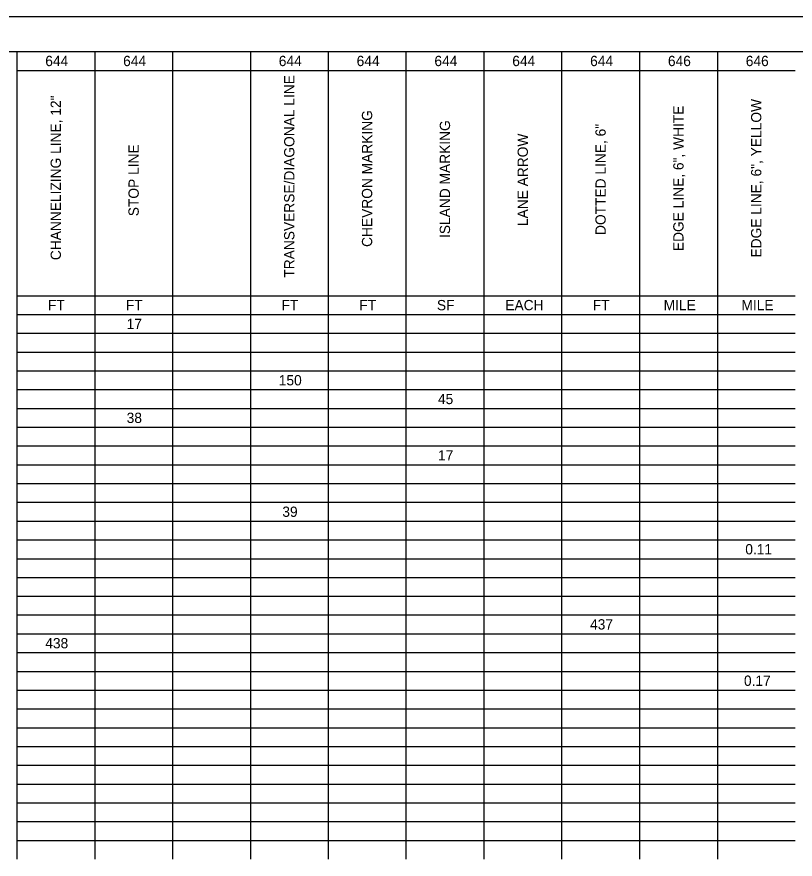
# Model space of a CAD drawing. Extents: x 0 to 34, y 0 to 22.
# Drawn here: x 14.09 to 25.28, y 9.88 to 22 of the extents above; entities that cross this region are included whole.
import ezdxf

# ---------------------------------------------------------------- set-up
doc = ezdxf.new("R2010")
doc.units = 0
for name, color, linetype in [('SH_Border', 7, 'Continuous'), ('SH_Cut_Line', 7, 'Continuous'), ('SH_Data', 7, 'Continuous')]:
    doc.layers.add(name, color=color, linetype=linetype)

msp = doc.modelspace()

# ---------------------------------------------------------------- linework, layer by layer
at = {"layer": 'SH_Border'}
msp.add_lwpolyline([(1.5, 21.5), (33.5, 21.5), (33.5, 0.5), (1.5, 0.5)], close=True, dxfattribs=at)
at = {"layer": 'SH_Cut_Line'}
msp.add_lwpolyline([(0, 0), (34, 0), (34, 22), (0, 22)], close=True, dxfattribs=at)
at = {"layer": 'SH_Data'}
for p, q in [((14.086, 21.5), (15.206, 21.5)), ((14.086, 21.5), (14.086, 21.23)), ((15.206, 21.5), (16.325, 21.5)), ((15.206, 21.5), (15.206, 21.23)), ((16.325, 21.5), (24.163, 21.5)), ((16.325, 21.5), (16.325, 21.23)), ((17.445, 21.5), (17.445, 21.23)), ((18.565, 21.5), (18.565, 21.23)), ((19.684, 21.5), (19.684, 21.23)), ((20.804, 21.5), (20.804, 21.23)), ((21.923, 21.5), (21.923, 21.23)), ((23.043, 21.5), (23.043, 21.23)), ((24.163, 21.5), (25.282, 21.5)), ((24.163, 21.5), (24.163, 21.23)), ((14.086, 21.23), (15.206, 21.23)), ((14.086, 21.23), (14.086, 20.96)), ((15.206, 21.23), (16.325, 21.23)), ((15.206, 21.23), (15.206, 20.96)), ((16.325, 21.23), (24.163, 21.23)), ((16.325, 21.23), (16.325, 20.96)), ((17.445, 21.23), (17.445, 20.96)), ((18.565, 21.23), (18.565, 20.96)), ((19.684, 21.23), (19.684, 20.96)), ((20.804, 21.23), (20.804, 20.96)), ((21.923, 21.23), (21.923, 20.96)), ((23.043, 21.23), (23.043, 20.96)), ((24.163, 21.23), (25.282, 21.23)), ((24.163, 21.23), (24.163, 20.96)), ((14.086, 20.96), (14.086, 20.69)), ((15.206, 20.96), (15.206, 20.69)), ((16.325, 20.96), (16.325, 20.69)), ((17.445, 20.96), (17.445, 20.69)), ((18.565, 20.96), (18.565, 20.69)), ((19.684, 20.96), (19.684, 20.69)), ((20.804, 20.96), (20.804, 20.69)), ((21.923, 20.96), (21.923, 20.69)), ((23.043, 20.96), (23.043, 20.69)), ((24.163, 20.96), (24.163, 20.69)), ((14.086, 20.69), (14.086, 20.419)), ((15.206, 20.69), (15.206, 20.419)), ((16.325, 20.69), (16.325, 20.419)), ((17.445, 20.69), (17.445, 20.419)), ((18.565, 20.69), (18.565, 20.419)), ((19.684, 20.69), (19.684, 20.419)), ((20.804, 20.69), (20.804, 20.419)), ((21.923, 20.69), (21.923, 20.419)), ((23.043, 20.69), (23.043, 20.419)), ((24.163, 20.69), (24.163, 20.419)), ((14.086, 20.419), (14.086, 20.149)), ((15.206, 20.419), (15.206, 20.149)), ((16.325, 20.419), (16.325, 20.149)), ((17.445, 20.419), (17.445, 20.149)), ((18.565, 20.419), (18.565, 20.149)), ((19.684, 20.419), (19.684, 20.149)), ((20.804, 20.419), (20.804, 20.149)), ((21.923, 20.419), (21.923, 20.149)), ((23.043, 20.419), (23.043, 20.149)), ((24.163, 20.419), (24.163, 20.149)), ((14.086, 20.149), (14.086, 19.879)), ((15.206, 20.149), (15.206, 19.879)), ((16.325, 20.149), (16.325, 19.879)), ((17.445, 20.149), (17.445, 19.879)), ((18.565, 20.149), (18.565, 19.879)), ((19.684, 20.149), (19.684, 19.879)), ((20.804, 20.149), (20.804, 19.879)), ((21.923, 20.149), (21.923, 19.879)), ((23.043, 20.149), (23.043, 19.879)), ((24.163, 20.149), (24.163, 19.879)), ((14.086, 19.879), (14.086, 19.609)), ((15.206, 19.879), (15.206, 19.609)), ((16.325, 19.879), (16.325, 19.609)), ((17.445, 19.879), (17.445, 19.609)), ((18.565, 19.879), (18.565, 19.609)), ((19.684, 19.879), (19.684, 19.609)), ((20.804, 19.879), (20.804, 19.609)), ((21.923, 19.879), (21.923, 19.609)), ((23.043, 19.879), (23.043, 19.609)), ((24.163, 19.879), (24.163, 19.609)), ((14.086, 19.609), (14.086, 19.338)), ((15.206, 19.609), (15.206, 19.338)), ((16.325, 19.609), (16.325, 19.338)), ((17.445, 19.609), (17.445, 19.338)), ((18.565, 19.609), (18.565, 19.338)), ((19.684, 19.609), (19.684, 19.338)), ((20.804, 19.609), (20.804, 19.338)), ((21.923, 19.609), (21.923, 19.338)), ((23.043, 19.609), (23.043, 19.338)), ((24.163, 19.609), (24.163, 19.338)), ((14.086, 19.338), (14.086, 19.068)), ((15.206, 19.338), (15.206, 19.068)), ((16.325, 19.338), (16.325, 19.068)), ((17.445, 19.338), (17.445, 19.068)), ((18.565, 19.338), (18.565, 19.068)), ((19.684, 19.338), (19.684, 19.068)), ((20.804, 19.338), (20.804, 19.068)), ((21.923, 19.338), (21.923, 19.068)), ((23.043, 19.338), (23.043, 19.068)), ((24.163, 19.338), (24.163, 19.068)), ((14.086, 19.068), (14.086, 18.798)), ((15.206, 19.068), (15.206, 18.798)), ((16.325, 19.068), (16.325, 18.798)), ((17.445, 19.068), (17.445, 18.798)), ((18.565, 19.068), (18.565, 18.798)), ((19.684, 19.068), (19.684, 18.798)), ((20.804, 19.068), (20.804, 18.798)), ((21.923, 19.068), (21.923, 18.798)), ((23.043, 19.068), (23.043, 18.798)), ((24.163, 19.068), (24.163, 18.798)), ((14.086, 18.798), (14.086, 18.528)), ((15.206, 18.798), (15.206, 18.528)), ((16.325, 18.798), (16.325, 18.528)), ((17.445, 18.798), (17.445, 18.528)), ((18.565, 18.798), (18.565, 18.528)), ((19.684, 18.798), (19.684, 18.528)), ((20.804, 18.798), (20.804, 18.528)), ((21.923, 18.798), (21.923, 18.528)), ((23.043, 18.798), (23.043, 18.528)), ((24.163, 18.798), (24.163, 18.528)), ((14.086, 18.528), (14.086, 18.257)), ((15.206, 18.528), (15.206, 18.257)), ((16.325, 18.528), (16.325, 18.257)), ((17.445, 18.528), (17.445, 18.257)), ((18.565, 18.528), (18.565, 18.257)), ((19.684, 18.528), (19.684, 18.257)), ((20.804, 18.528), (20.804, 18.257)), ((21.923, 18.528), (21.923, 18.257)), ((23.043, 18.528), (23.043, 18.257)), ((24.163, 18.528), (24.163, 18.257)), ((14.086, 18.257), (14.086, 17.987)), ((15.206, 18.257), (15.206, 17.987)), ((16.325, 18.257), (16.325, 17.987)), ((17.445, 18.257), (17.445, 17.987)), ((18.565, 18.257), (18.565, 17.987)), ((19.684, 18.257), (19.684, 17.987)), ((20.804, 18.257), (20.804, 17.987)), ((21.923, 18.257), (21.923, 17.987)), ((23.043, 18.257), (23.043, 17.987)), ((24.163, 18.257), (24.163, 17.987)), ((14.086, 17.987), (15.206, 17.987)), ((14.086, 17.987), (14.086, 17.717)), ((15.206, 17.987), (16.325, 17.987)), ((15.206, 17.987), (15.206, 17.717)), ((16.325, 17.987), (24.163, 17.987)), ((16.325, 17.987), (16.325, 17.717)), ((17.445, 17.987), (17.445, 17.717)), ((18.565, 17.987), (18.565, 17.717)), ((19.684, 17.987), (19.684, 17.717)), ((20.804, 17.987), (20.804, 17.717)), ((21.923, 17.987), (21.923, 17.717)), ((23.043, 17.987), (23.043, 17.717)), ((24.163, 17.987), (25.282, 17.987)), ((24.163, 17.987), (24.163, 17.717)), ((14.086, 17.717), (15.206, 17.717)), ((14.086, 17.717), (14.086, 17.447)), ((15.206, 17.717), (16.325, 17.717)), ((15.206, 17.717), (15.206, 17.447)), ((16.325, 17.717), (24.163, 17.717)), ((16.325, 17.717), (16.325, 17.447)), ((17.445, 17.717), (17.445, 17.447)), ((18.565, 17.717), (18.565, 17.447)), ((19.684, 17.717), (19.684, 17.447)), ((20.804, 17.717), (20.804, 17.447)), ((21.923, 17.717), (21.923, 17.447)), ((23.043, 17.717), (23.043, 17.447)), ((24.163, 17.717), (25.282, 17.717)), ((24.163, 17.717), (24.163, 17.447)), ((14.086, 17.447), (15.206, 17.447)), ((14.086, 17.447), (14.086, 17.176)), ((15.206, 17.447), (16.325, 17.447)), ((15.206, 17.447), (15.206, 17.176)), ((16.325, 17.447), (24.163, 17.447)), ((16.325, 17.447), (16.325, 17.176)), ((17.445, 17.447), (17.445, 17.176)), ((18.565, 17.447), (18.565, 17.176)), ((19.684, 17.447), (19.684, 17.176)), ((20.804, 17.447), (20.804, 17.176)), ((21.923, 17.447), (21.923, 17.176)), ((23.043, 17.447), (23.043, 17.176)), ((24.163, 17.447), (25.282, 17.447)), ((24.163, 17.447), (24.163, 17.176)), ((14.086, 17.176), (15.206, 17.176)), ((14.086, 17.176), (14.086, 16.906)), ((15.206, 17.176), (16.325, 17.176)), ((15.206, 17.176), (15.206, 16.906)), ((16.325, 17.176), (24.163, 17.176)), ((16.325, 17.176), (16.325, 16.906)), ((17.445, 17.176), (17.445, 16.906)), ((18.565, 17.176), (18.565, 16.906)), ((19.684, 17.176), (19.684, 16.906)), ((20.804, 17.176), (20.804, 16.906)), ((21.923, 17.176), (21.923, 16.906)), ((23.043, 17.176), (23.043, 16.906)), ((24.163, 17.176), (25.282, 17.176)), ((24.163, 17.176), (24.163, 16.906)), ((14.086, 16.906), (15.206, 16.906)), ((14.086, 16.906), (14.086, 16.636)), ((15.206, 16.906), (16.325, 16.906)), ((15.206, 16.906), (15.206, 16.636)), ((16.325, 16.906), (24.163, 16.906)), ((16.325, 16.906), (16.325, 16.636)), ((17.445, 16.906), (17.445, 16.636)), ((18.565, 16.906), (18.565, 16.636)), ((19.684, 16.906), (19.684, 16.636)), ((20.804, 16.906), (20.804, 16.636)), ((21.923, 16.906), (21.923, 16.636)), ((23.043, 16.906), (23.043, 16.636)), ((24.163, 16.906), (25.282, 16.906)), ((24.163, 16.906), (24.163, 16.636)), ((14.086, 16.636), (15.206, 16.636)), ((14.086, 16.636), (14.086, 16.365)), ((15.206, 16.636), (16.325, 16.636)), ((15.206, 16.636), (15.206, 16.365)), ((16.325, 16.636), (24.163, 16.636)), ((16.325, 16.636), (16.325, 16.365)), ((17.445, 16.636), (17.445, 16.365)), ((18.565, 16.636), (18.565, 16.365)), ((19.684, 16.636), (19.684, 16.365)), ((20.804, 16.636), (20.804, 16.365)), ((21.923, 16.636), (21.923, 16.365)), ((23.043, 16.636), (23.043, 16.365)), ((24.163, 16.636), (25.282, 16.636)), ((24.163, 16.636), (24.163, 16.365)), ((14.086, 16.365), (15.206, 16.365)), ((14.086, 16.365), (14.086, 16.095)), ((15.206, 16.365), (16.325, 16.365)), ((15.206, 16.365), (15.206, 16.095)), ((16.325, 16.365), (24.163, 16.365)), ((16.325, 16.365), (16.325, 16.095)), ((17.445, 16.365), (17.445, 16.095)), ((18.565, 16.365), (18.565, 16.095)), ((19.684, 16.365), (19.684, 16.095)), ((20.804, 16.365), (20.804, 16.095)), ((21.923, 16.365), (21.923, 16.095)), ((23.043, 16.365), (23.043, 16.095)), ((24.163, 16.365), (25.282, 16.365)), ((24.163, 16.365), (24.163, 16.095)), ((14.086, 16.095), (15.206, 16.095)), ((14.086, 16.095), (14.086, 15.825)), ((15.206, 16.095), (16.325, 16.095)), ((15.206, 16.095), (15.206, 15.825)), ((16.325, 16.095), (24.163, 16.095)), ((16.325, 16.095), (16.325, 15.825)), ((17.445, 16.095), (17.445, 15.825)), ((18.565, 16.095), (18.565, 15.825)), ((19.684, 16.095), (19.684, 15.825)), ((20.804, 16.095), (20.804, 15.825)), ((21.923, 16.095), (21.923, 15.825)), ((23.043, 16.095), (23.043, 15.825)), ((24.163, 16.095), (25.282, 16.095)), ((24.163, 16.095), (24.163, 15.825)), ((14.086, 15.825), (15.206, 15.825)), ((14.086, 15.825), (14.086, 15.555)), ((15.206, 15.825), (16.325, 15.825)), ((15.206, 15.825), (15.206, 15.555)), ((16.325, 15.825), (24.163, 15.825)), ((16.325, 15.825), (16.325, 15.555)), ((17.445, 15.825), (17.445, 15.555)), ((18.565, 15.825), (18.565, 15.555)), ((19.684, 15.825), (19.684, 15.555)), ((20.804, 15.825), (20.804, 15.555)), ((21.923, 15.825), (21.923, 15.555)), ((23.043, 15.825), (23.043, 15.555)), ((24.163, 15.825), (25.282, 15.825)), ((24.163, 15.825), (24.163, 15.555)), ((14.086, 15.555), (15.206, 15.555)), ((14.086, 15.555), (14.086, 15.284)), ((15.206, 15.555), (16.325, 15.555)), ((15.206, 15.555), (15.206, 15.284)), ((16.325, 15.555), (24.163, 15.555)), ((16.325, 15.555), (16.325, 15.284)), ((17.445, 15.555), (17.445, 15.284)), ((18.565, 15.555), (18.565, 15.284)), ((19.684, 15.555), (19.684, 15.284)), ((20.804, 15.555), (20.804, 15.284)), ((21.923, 15.555), (21.923, 15.284)), ((23.043, 15.555), (23.043, 15.284)), ((24.163, 15.555), (25.282, 15.555)), ((24.163, 15.555), (24.163, 15.284)), ((14.086, 15.284), (15.206, 15.284)), ((14.086, 15.284), (14.086, 15.014)), ((15.206, 15.284), (16.325, 15.284)), ((15.206, 15.284), (15.206, 15.014)), ((16.325, 15.284), (24.163, 15.284)), ((16.325, 15.284), (16.325, 15.014)), ((17.445, 15.284), (17.445, 15.014)), ((18.565, 15.284), (18.565, 15.014)), ((19.684, 15.284), (19.684, 15.014)), ((20.804, 15.284), (20.804, 15.014)), ((21.923, 15.284), (21.923, 15.014)), ((23.043, 15.284), (23.043, 15.014)), ((24.163, 15.284), (25.282, 15.284)), ((24.163, 15.284), (24.163, 15.014)), ((14.086, 15.014), (15.206, 15.014)), ((14.086, 15.014), (14.086, 14.744)), ((15.206, 15.014), (16.325, 15.014)), ((15.206, 15.014), (15.206, 14.744)), ((16.325, 15.014), (24.163, 15.014)), ((16.325, 15.014), (16.325, 14.744)), ((17.445, 15.014), (17.445, 14.744)), ((18.565, 15.014), (18.565, 14.744)), ((19.684, 15.014), (19.684, 14.744)), ((20.804, 15.014), (20.804, 14.744)), ((21.923, 15.014), (21.923, 14.744)), ((23.043, 15.014), (23.043, 14.744)), ((24.163, 15.014), (25.282, 15.014)), ((24.163, 15.014), (24.163, 14.744)), ((14.086, 14.744), (15.206, 14.744)), ((14.086, 14.744), (14.086, 14.474)), ((15.206, 14.744), (16.325, 14.744)), ((15.206, 14.744), (15.206, 14.474)), ((16.325, 14.744), (24.163, 14.744)), ((16.325, 14.744), (16.325, 14.474)), ((17.445, 14.744), (17.445, 14.474)), ((18.565, 14.744), (18.565, 14.474)), ((19.684, 14.744), (19.684, 14.474)), ((20.804, 14.744), (20.804, 14.474)), ((21.923, 14.744), (21.923, 14.474)), ((23.043, 14.744), (23.043, 14.474)), ((24.163, 14.744), (25.282, 14.744)), ((24.163, 14.744), (24.163, 14.474)), ((14.086, 14.474), (15.206, 14.474)), ((14.086, 14.474), (14.086, 14.203)), ((15.206, 14.474), (16.325, 14.474)), ((15.206, 14.474), (15.206, 14.203)), ((16.325, 14.474), (24.163, 14.474)), ((16.325, 14.474), (16.325, 14.203)), ((17.445, 14.474), (17.445, 14.203)), ((18.565, 14.474), (18.565, 14.203)), ((19.684, 14.474), (19.684, 14.203)), ((20.804, 14.474), (20.804, 14.203)), ((21.923, 14.474), (21.923, 14.203)), ((23.043, 14.474), (23.043, 14.203)), ((24.163, 14.474), (25.282, 14.474)), ((24.163, 14.474), (24.163, 14.203)), ((14.086, 14.203), (15.206, 14.203)), ((14.086, 14.203), (14.086, 13.933)), ((15.206, 14.203), (16.325, 14.203)), ((15.206, 14.203), (15.206, 13.933)), ((16.325, 14.203), (24.163, 14.203)), ((16.325, 14.203), (16.325, 13.933)), ((17.445, 14.203), (17.445, 13.933)), ((18.565, 14.203), (18.565, 13.933)), ((19.684, 14.203), (19.684, 13.933)), ((20.804, 14.203), (20.804, 13.933)), ((21.923, 14.203), (21.923, 13.933)), ((23.043, 14.203), (23.043, 13.933)), ((24.163, 14.203), (25.282, 14.203)), ((24.163, 14.203), (24.163, 13.933)), ((14.086, 13.933), (15.206, 13.933)), ((14.086, 13.933), (14.086, 13.663)), ((15.206, 13.933), (16.325, 13.933)), ((15.206, 13.933), (15.206, 13.663)), ((16.325, 13.933), (24.163, 13.933)), ((16.325, 13.933), (16.325, 13.663)), ((17.445, 13.933), (17.445, 13.663)), ((18.565, 13.933), (18.565, 13.663)), ((19.684, 13.933), (19.684, 13.663)), ((20.804, 13.933), (20.804, 13.663)), ((21.923, 13.933), (21.923, 13.663)), ((23.043, 13.933), (23.043, 13.663)), ((24.163, 13.933), (25.282, 13.933)), ((24.163, 13.933), (24.163, 13.663)), ((14.086, 13.663), (15.206, 13.663)), ((14.086, 13.663), (14.086, 13.393)), ((15.206, 13.663), (16.325, 13.663)), ((15.206, 13.663), (15.206, 13.393)), ((16.325, 13.663), (24.163, 13.663)), ((16.325, 13.663), (16.325, 13.393)), ((17.445, 13.663), (17.445, 13.393)), ((18.565, 13.663), (18.565, 13.393)), ((19.684, 13.663), (19.684, 13.393)), ((20.804, 13.663), (20.804, 13.393)), ((21.923, 13.663), (21.923, 13.393)), ((23.043, 13.663), (23.043, 13.393)), ((24.163, 13.663), (25.282, 13.663)), ((24.163, 13.663), (24.163, 13.393)), ((14.086, 13.393), (15.206, 13.393)), ((14.086, 13.393), (14.086, 13.122)), ((15.206, 13.393), (16.325, 13.393)), ((15.206, 13.393), (15.206, 13.122)), ((16.325, 13.393), (24.163, 13.393)), ((16.325, 13.393), (16.325, 13.122)), ((17.445, 13.393), (17.445, 13.122)), ((18.565, 13.393), (18.565, 13.122)), ((19.684, 13.393), (19.684, 13.122)), ((20.804, 13.393), (20.804, 13.122)), ((21.923, 13.393), (21.923, 13.122)), ((23.043, 13.393), (23.043, 13.122)), ((24.163, 13.393), (25.282, 13.393)), ((24.163, 13.393), (24.163, 13.122)), ((14.086, 13.122), (15.206, 13.122)), ((14.086, 13.122), (14.086, 12.852)), ((15.206, 13.122), (16.325, 13.122)), ((15.206, 13.122), (15.206, 12.852)), ((16.325, 13.122), (24.163, 13.122)), ((16.325, 13.122), (16.325, 12.852)), ((17.445, 13.122), (17.445, 12.852)), ((18.565, 13.122), (18.565, 12.852)), ((19.684, 13.122), (19.684, 12.852)), ((20.804, 13.122), (20.804, 12.852)), ((21.923, 13.122), (21.923, 12.852)), ((23.043, 13.122), (23.043, 12.852)), ((24.163, 13.122), (25.282, 13.122)), ((24.163, 13.122), (24.163, 12.852)), ((14.086, 12.852), (15.206, 12.852)), ((14.086, 12.852), (14.086, 12.582)), ((15.206, 12.852), (16.325, 12.852)), ((15.206, 12.852), (15.206, 12.582)), ((16.325, 12.852), (24.163, 12.852)), ((16.325, 12.852), (16.325, 12.582)), ((17.445, 12.852), (17.445, 12.582)), ((18.565, 12.852), (18.565, 12.582)), ((19.684, 12.852), (19.684, 12.582)), ((20.804, 12.852), (20.804, 12.582)), ((21.923, 12.852), (21.923, 12.582)), ((23.043, 12.852), (23.043, 12.582)), ((24.163, 12.852), (25.282, 12.852)), ((24.163, 12.852), (24.163, 12.582)), ((14.086, 12.582), (15.206, 12.582)), ((14.086, 12.582), (14.086, 12.312)), ((15.206, 12.582), (16.325, 12.582)), ((15.206, 12.582), (15.206, 12.312)), ((16.325, 12.582), (24.163, 12.582)), ((16.325, 12.582), (16.325, 12.312)), ((17.445, 12.582), (17.445, 12.312)), ((18.565, 12.582), (18.565, 12.312)), ((19.684, 12.582), (19.684, 12.312)), ((20.804, 12.582), (20.804, 12.312)), ((21.923, 12.582), (21.923, 12.312)), ((23.043, 12.582), (23.043, 12.312)), ((24.163, 12.582), (25.282, 12.582)), ((24.163, 12.582), (24.163, 12.312)), ((14.086, 12.312), (15.206, 12.312)), ((14.086, 12.312), (14.086, 12.041)), ((15.206, 12.312), (16.325, 12.312)), ((15.206, 12.312), (15.206, 12.041)), ((16.325, 12.312), (24.163, 12.312)), ((16.325, 12.312), (16.325, 12.041)), ((17.445, 12.312), (17.445, 12.041)), ((18.565, 12.312), (18.565, 12.041)), ((19.684, 12.312), (19.684, 12.041)), ((20.804, 12.312), (20.804, 12.041)), ((21.923, 12.312), (21.923, 12.041)), ((23.043, 12.312), (23.043, 12.041)), ((24.163, 12.312), (25.282, 12.312)), ((24.163, 12.312), (24.163, 12.041)), ((14.086, 12.041), (15.206, 12.041)), ((14.086, 12.041), (14.086, 11.771)), ((15.206, 12.041), (16.325, 12.041)), ((15.206, 12.041), (15.206, 11.771)), ((16.325, 12.041), (24.163, 12.041)), ((16.325, 12.041), (16.325, 11.771)), ((17.445, 12.041), (17.445, 11.771)), ((18.565, 12.041), (18.565, 11.771)), ((19.684, 12.041), (19.684, 11.771)), ((20.804, 12.041), (20.804, 11.771)), ((21.923, 12.041), (21.923, 11.771)), ((23.043, 12.041), (23.043, 11.771)), ((24.163, 12.041), (25.282, 12.041)), ((24.163, 12.041), (24.163, 11.771)), ((14.086, 11.771), (15.206, 11.771)), ((14.086, 11.771), (14.086, 11.501)), ((15.206, 11.771), (16.325, 11.771)), ((15.206, 11.771), (15.206, 11.501)), ((16.325, 11.771), (24.163, 11.771)), ((16.325, 11.771), (16.325, 11.501)), ((17.445, 11.771), (17.445, 11.501)), ((18.565, 11.771), (18.565, 11.501)), ((19.684, 11.771), (19.684, 11.501)), ((20.804, 11.771), (20.804, 11.501)), ((21.923, 11.771), (21.923, 11.501)), ((23.043, 11.771), (23.043, 11.501)), ((24.163, 11.771), (25.282, 11.771)), ((24.163, 11.771), (24.163, 11.501)), ((14.086, 11.501), (15.206, 11.501)), ((14.086, 11.501), (14.086, 11.231)), ((15.206, 11.501), (16.325, 11.501)), ((15.206, 11.501), (15.206, 11.231)), ((16.325, 11.501), (24.163, 11.501)), ((16.325, 11.501), (16.325, 11.231)), ((17.445, 11.501), (17.445, 11.231)), ((18.565, 11.501), (18.565, 11.231)), ((19.684, 11.501), (19.684, 11.231)), ((20.804, 11.501), (20.804, 11.231)), ((21.923, 11.501), (21.923, 11.231)), ((23.043, 11.501), (23.043, 11.231)), ((24.163, 11.501), (25.282, 11.501)), ((24.163, 11.501), (24.163, 11.231)), ((14.086, 11.231), (15.206, 11.231)), ((14.086, 11.231), (14.086, 10.96)), ((15.206, 11.231), (16.325, 11.231)), ((15.206, 11.231), (15.206, 10.96)), ((16.325, 11.231), (24.163, 11.231)), ((16.325, 11.231), (16.325, 10.96)), ((17.445, 11.231), (17.445, 10.96)), ((18.565, 11.231), (18.565, 10.96)), ((19.684, 11.231), (19.684, 10.96)), ((20.804, 11.231), (20.804, 10.96)), ((21.923, 11.231), (21.923, 10.96)), ((23.043, 11.231), (23.043, 10.96)), ((24.163, 11.231), (25.282, 11.231)), ((24.163, 11.231), (24.163, 10.96)), ((14.086, 10.96), (15.206, 10.96)), ((14.086, 10.96), (14.086, 10.69)), ((15.206, 10.96), (16.325, 10.96)), ((15.206, 10.96), (15.206, 10.69)), ((16.325, 10.96), (24.163, 10.96)), ((16.325, 10.96), (16.325, 10.69)), ((17.445, 10.96), (17.445, 10.69)), ((18.565, 10.96), (18.565, 10.69)), ((19.684, 10.96), (19.684, 10.69)), ((20.804, 10.96), (20.804, 10.69)), ((21.923, 10.96), (21.923, 10.69)), ((23.043, 10.96), (23.043, 10.69)), ((24.163, 10.96), (25.282, 10.96)), ((24.163, 10.96), (24.163, 10.69)), ((14.086, 10.69), (15.206, 10.69)), ((14.086, 10.69), (14.086, 10.42)), ((15.206, 10.69), (16.325, 10.69)), ((15.206, 10.69), (15.206, 10.42)), ((16.325, 10.69), (24.163, 10.69)), ((16.325, 10.69), (16.325, 10.42)), ((17.445, 10.69), (17.445, 10.42)), ((18.565, 10.69), (18.565, 10.42)), ((19.684, 10.69), (19.684, 10.42)), ((20.804, 10.69), (20.804, 10.42)), ((21.923, 10.69), (21.923, 10.42)), ((23.043, 10.69), (23.043, 10.42)), ((24.163, 10.69), (25.282, 10.69)), ((24.163, 10.69), (24.163, 10.42)), ((14.086, 10.42), (15.206, 10.42)), ((14.086, 10.42), (14.086, 10.15)), ((15.206, 10.42), (16.325, 10.42)), ((15.206, 10.42), (15.206, 10.15)), ((16.325, 10.42), (24.163, 10.42)), ((16.325, 10.42), (16.325, 10.15)), ((17.445, 10.42), (17.445, 10.15)), ((18.565, 10.42), (18.565, 10.15)), ((19.684, 10.42), (19.684, 10.15)), ((20.804, 10.42), (20.804, 10.15)), ((21.923, 10.42), (21.923, 10.15)), ((23.043, 10.42), (23.043, 10.15)), ((24.163, 10.42), (25.282, 10.42)), ((24.163, 10.42), (24.163, 10.15)), ((14.086, 10.15), (15.206, 10.15)), ((14.086, 10.15), (14.086, 9.879)), ((15.206, 10.15), (16.325, 10.15)), ((15.206, 10.15), (15.206, 9.879)), ((16.325, 10.15), (24.163, 10.15)), ((16.325, 10.15), (16.325, 9.879)), ((17.445, 10.15), (17.445, 9.879)), ((18.565, 10.15), (18.565, 9.879)), ((19.684, 10.15), (19.684, 9.879)), ((20.804, 10.15), (20.804, 9.879)), ((21.923, 10.15), (21.923, 9.879)), ((23.043, 10.15), (23.043, 9.879)), ((24.163, 10.15), (25.282, 10.15)), ((24.163, 10.15), (24.163, 9.879))]:
    msp.add_line(p, q, dxfattribs=at)

# ---------------------------------------------------------------- texts
for s, p in [('644', (14.495, 21.291)), ('644', (15.615, 21.291)), ('644', (17.854, 21.291)), ('644', (18.974, 21.291)), ('644', (20.093, 21.291)), ('644', (21.213, 21.291)), ('644', (22.333, 21.291)), ('646', (23.452, 21.291)), ('646', (24.572, 21.291)), ('FT', (14.534, 17.778)), ('FT', (15.654, 17.778)), ('FT', (17.893, 17.778)), ('FT', (19.013, 17.778)), ('SF', (20.129, 17.778)), ('EACH', (21.113, 17.778)), ('FT', (22.371, 17.778)), ('MILE', (23.391, 17.778)), ('MILE', (24.51, 17.778)), ('17', (15.666, 17.508)), ('150', (17.854, 16.697)), ('45', (20.144, 16.427)), ('38', (15.666, 16.156)), ('17', (20.145, 15.616)), ('39', (17.905, 14.805)), ('0.11', (24.565, 14.265)), ('437', (22.332, 13.184)), ('438', (14.495, 12.913)), ('0.17', (24.546, 12.373))]:
    msp.add_text(s, height=0.148, dxfattribs=at).set_placement(p)
for s, p in [('TRANSVERSE/DIAGONAL LINE', (18.079, 18.247)), ('CHANNELIZING LINE, 12"', (14.72, 18.499)), ('EDGE LINE, 6", YELLOW', (24.796, 18.537)), ('CHEVRON MARKING', (19.198, 18.689)), ('EDGE LINE, 6", WHITE', (23.677, 18.629)), ('ISLAND MARKING', (20.318, 18.818)), ('DOTTED LINE, 6"', (22.557, 18.861)), ('LANE ARROW', (21.438, 18.989)), ('STOP LINE', (15.84, 19.131))]:
    msp.add_text(s, height=0.148, rotation=90, dxfattribs=at).set_placement(p)

doc.saveas('drawing.dxf')
